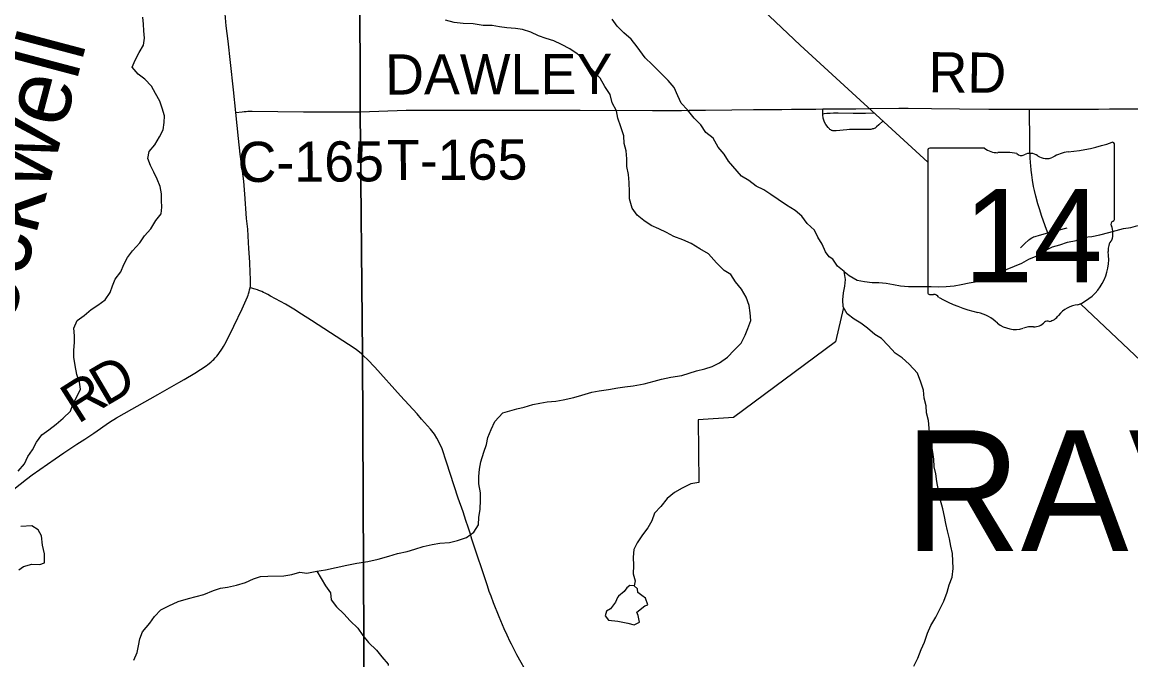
# Model space of a CAD drawing. Extents: x 0 to 34, y 0 to 22.
# Drawn here: x 4.548 to 6.114, y 15.953 to 16.855 of the extents above; entities that cross this region are included whole.
import ezdxf

# ---------------------------------------------------------------- set-up
doc = ezdxf.new("R2010")
doc.units = 0
for name, color, linetype in [('GM_X_Corporation', 7, 'Continuous'), ('GM_X_County_Road', 7, 'Continuous'), ('GM_X_County_Road_Text', 7, 'Continuous'), ('GM_X_Major_Lake', 7, 'Continuous'), ('GM_X_Major_Lake_Text', 7, 'Continuous'), ('GM_X_Minor_Lake', 7, 'Continuous'), ('GM_X_Minor_River', 7, 'Continuous'), ('GM_X_State_Shield', 7, 'Continuous'), ('GM_X_Township_Road', 7, 'Continuous'), ('GM_X_Township_Road_Text', 7, 'Continuous'), ('GM_X_Township_Text', 7, 'Continuous'), ('SH_Text', 7, 'Continuous')]:
    doc.layers.add(name, color=color, linetype=linetype)

msp = doc.modelspace()

# ---------------------------------------------------------------- linework, layer by layer
at = {"layer": 'GM_X_Corporation'}
for points in [[(2.1, 14.1), (5.0398, 14.1), (5.0411, 14.425), (5.0381, 14.4922), (5.0378, 14.5635), (5.0395, 14.6051), (5.0366, 14.7668), (5.0353, 14.97), (5.0288, 16.3849), (5.0258, 16.7286), (5.0235, 17.4989), (5.0235, 17.5004), (5.0224, 17.5004), (4.9697, 17.5009), (4.8689, 17.5017), (4.8462, 17.5018), (4.8313, 17.5017), (4.8033, 17.5014), (4.7857, 17.5004), (4.7764, 17.4996), (4.7708, 17.4988), (4.7665, 17.4977), (4.718, 17.4962), (3.7119, 17.4934)], [(5.0235, 17.4989), (5.0258, 16.7286), (5.0288, 16.3849), (5.0353, 14.97)]]:
    msp.add_lwpolyline(points, dxfattribs=at)
at = {"layer": 'GM_X_County_Road'}
for points in [[(4.8499, 16.7267), (4.8465, 16.7588), (4.8424, 16.7977), (4.8391, 16.8279), (4.8365, 16.8495), (4.835, 16.8662)], [(4.8499, 16.7267), (4.8591, 16.728), (4.8617, 16.7283), (4.8644, 16.7285), (4.8671, 16.7287), (4.873, 16.7287), (4.9456, 16.7279), (5.026, 16.728)], [(4.8701, 16.4792), (4.8705, 16.4816), (4.8707, 16.4839), (4.8708, 16.4864), (4.8708, 16.489), (4.8708, 16.4919), (4.8703, 16.5005), (4.8696, 16.5155), (4.8685, 16.5346), (4.8681, 16.5433), (4.8668, 16.5619), (4.8653, 16.5773), (4.8628, 16.612), (4.8624, 16.6172), (4.862, 16.6244), (4.8614, 16.6293), (4.8609, 16.6336), (4.8563, 16.668), (4.8537, 16.6902), (4.8499, 16.7267)], [(4.5363, 16.1946), (4.5544, 16.2088), (4.5624, 16.2148), (4.5948, 16.2376), (4.607, 16.246), (4.6256, 16.258), (4.6368, 16.2652), (4.6493, 16.2737), (4.6718, 16.2891), (4.6814, 16.2952), (4.6922, 16.3015), (4.7398, 16.3282), (4.7694, 16.3452), (4.777, 16.3496), (4.7919, 16.3585), (4.8081, 16.3689), (4.8106, 16.3708), (4.8125, 16.3722), (4.8151, 16.3744), (4.8172, 16.3762), (4.819, 16.378), (4.821, 16.3801), (4.8231, 16.3825), (4.825, 16.3848), (4.8271, 16.3877), (4.8293, 16.3908), (4.831, 16.3936), (4.8325, 16.396), (4.8344, 16.3996), (4.8366, 16.4036), (4.8471, 16.4248), (4.8588, 16.4495), (4.8664, 16.4662), (4.8673, 16.4689), (4.868, 16.4708), (4.8687, 16.4735), (4.8694, 16.4762), (4.8701, 16.4792)], [(5.029, 16.3843), (5.0273, 16.3858), (5.0222, 16.3899), (5.0184, 16.3927), (4.957, 16.4329), (4.9429, 16.4421), (4.9319, 16.4491), (4.9201, 16.456), (4.8991, 16.4675), (4.8954, 16.4695), (4.8915, 16.4715), (4.8892, 16.4725), (4.8866, 16.4737), (4.8827, 16.4754), (4.8804, 16.4762), (4.8774, 16.4772), (4.8752, 16.4779), (4.8728, 16.4786), (4.8701, 16.4792)], [(5.2632, 15.9313), (5.247, 15.9603), (5.2435, 15.9669), (5.2393, 15.9754), (5.2376, 15.9787), (5.2332, 15.9883), (5.2291, 15.9973), (5.222, 16.0139), (5.2139, 16.034), (5.2104, 16.0433), (5.208, 16.0498), (5.2053, 16.0577), (5.1835, 16.1237), (5.1808, 16.1322), (5.178, 16.1409), (5.1749, 16.1504), (5.1709, 16.1624), (5.1641, 16.1818), (5.1584, 16.1994), (5.1476, 16.2329), (5.1415, 16.2514), (5.1382, 16.2588), (5.1341, 16.2666), (5.1304, 16.2723), (5.1251, 16.2793), (5.1123, 16.2937), (5.1061, 16.3009), (5.0825, 16.3264), (5.0461, 16.367), (5.0361, 16.3777), (5.0309, 16.3827), (5.0299, 16.3835), (5.029, 16.3843)]]:
    msp.add_lwpolyline(points, dxfattribs=at)
at = {"layer": 'GM_X_Major_Lake'}
msp.add_lwpolyline([(4.5428, 16.22), (4.5515, 16.2303), (4.5563, 16.2406), (4.5627, 16.2501), (4.5683, 16.2611), (4.5761, 16.2714), (4.5859, 16.2783), (4.5961, 16.2864), (4.6062, 16.2948), (4.6164, 16.3047), (4.6197, 16.3142), (4.626, 16.326), (4.6305, 16.3359), (4.6293, 16.3458), (4.6254, 16.3567), (4.623, 16.3692), (4.6214, 16.381), (4.6214, 16.3908), (4.6224, 16.4018), (4.622, 16.4113), (4.6211, 16.4223), (4.6259, 16.433), (4.6357, 16.4399), (4.6455, 16.4487), (4.6553, 16.4548), (4.6655, 16.4621), (4.6726, 16.4724), (4.6759, 16.4819), (4.6796, 16.4914), (4.6875, 16.5017), (4.6919, 16.5123), (4.6968, 16.5219), (4.7039, 16.5314), (4.7144, 16.5429), (4.7211, 16.5528), (4.7298, 16.5627), (4.7372, 16.5741), (4.7444, 16.5837), (4.7454, 16.5931), (4.745, 16.6026), (4.7449, 16.6121), (4.7433, 16.6223), (4.7387, 16.6325), (4.7344, 16.6424), (4.7294, 16.6522), (4.7256, 16.662), (4.7274, 16.6719), (4.7356, 16.6814), (4.742, 16.6925), (4.7472, 16.7024), (4.7486, 16.7126), (4.7493, 16.7221), (4.7462, 16.7331), (4.7427, 16.7429), (4.7366, 16.7539), (4.7308, 16.764), (4.7217, 16.7742), (4.7122, 16.781), (4.7037, 16.7911), (4.7078, 16.801), (4.7134, 16.8117), (4.7194, 16.822), (4.7208, 16.8318), (4.72, 16.8425), (4.7195, 16.8519), (4.7187, 16.8618)], dxfattribs=at)
at = {"layer": 'GM_X_Minor_Lake'}
msp.add_line((5.389, 16.0415), (5.3864, 16.0347), dxfattribs=at)
for points in [[(4.5436, 16.0804), (4.55, 16.0854), (4.5617, 16.0885), (4.573, 16.0879), (4.5798, 16.0906), (4.5797, 16.1031), (4.577, 16.1156), (4.5754, 16.1288), (4.5707, 16.1371), (4.562, 16.1428), (4.5465, 16.1419)], [(5.3864, 16.0347), (5.3793, 16.0255), (5.3733, 16.022), (5.3714, 16.0156), (5.3764, 16.0092), (5.3897, 16.0081), (5.4037, 16.0052), (5.4124, 16.0026), (5.4203, 16.0065), (5.418, 16.0159), (5.4161, 16.0209), (5.4277, 16.0297), (5.4319, 16.0312), (5.4288, 16.0407), (5.4234, 16.0444), (5.4177, 16.0485), (5.4173, 16.0535), (5.4124, 16.058), (5.4063, 16.0583), (5.4022, 16.0549), (5.3984, 16.0499), (5.3905, 16.0434), (5.389, 16.0415)]]:
    msp.add_lwpolyline(points, dxfattribs=at)
at = {"layer": 'GM_X_Minor_River'}
for p, q in [((5.7081, 16.4513), (5.6969, 16.403)), ((5.6969, 16.403), (5.5528, 16.2957))]:
    msp.add_line(p, q, dxfattribs=at)
for points in [[(5.5558, 16.4876), (5.5493, 16.4981), (5.5398, 16.5037), (5.5287, 16.5146), (5.5177, 16.5271), (5.5055, 16.5342), (5.4929, 16.5417), (5.4812, 16.5469), (5.4686, 16.5517), (5.458, 16.5573), (5.4474, 16.5625), (5.4367, 16.5674), (5.4264, 16.5741), (5.4169, 16.5817), (5.4097, 16.5915), (5.4058, 16.6051), (5.4061, 16.6149), (5.4056, 16.6282), (5.4047, 16.6392), (5.402, 16.6505), (5.4023, 16.6615), (5.4011, 16.6725), (5.3983, 16.6831), (5.3979, 16.6937), (5.3936, 16.7066), (5.3897, 16.7191), (5.3878, 16.7293), (5.3816, 16.7406), (5.3789, 16.7524), (5.3712, 16.7637), (5.3647, 16.7754), (5.3494, 16.7916), (5.3414, 16.8021), (5.3319, 16.81), (5.3216, 16.8168), (5.3098, 16.8231), (5.2992, 16.8283), (5.2882, 16.8313), (5.2775, 16.8354), (5.2665, 16.8406), (5.2548, 16.8443), (5.2449, 16.8458), (5.2328, 16.8464), (5.2222, 16.8482), (5.2119, 16.85), (5.1991, 16.8499), (5.1854, 16.8521), (5.1711, 16.8528), (5.1585, 16.8542), (5.146, 16.8575)], [(5.6879, 16.5229), (5.683, 16.5302), (5.678, 16.5408), (5.6719, 16.5506), (5.6673, 16.5605), (5.657, 16.5702), (5.6493, 16.5804), (5.6398, 16.5883), (5.6276, 16.5958), (5.6158, 16.604), (5.6056, 16.6112), (5.5957, 16.6175), (5.585, 16.6228), (5.5747, 16.6306), (5.5641, 16.637), (5.5458, 16.6581), (5.5396, 16.6679), (5.5312, 16.6781), (5.5239, 16.6905), (5.5136, 16.6988), (5.5067, 16.7094), (5.4972, 16.7188), (5.4877, 16.7305), (5.4789, 16.7402), (5.4743, 16.7504), (5.4692, 16.7622), (5.4608, 16.772), (5.4494, 16.7836), (5.4379, 16.7949), (5.428, 16.8043), (5.4169, 16.8198), (5.4081, 16.8307), (5.3982, 16.8393), (5.3887, 16.8488), (5.3814, 16.8586)], [(5.709, 16.502), (5.7162, 16.4964), (5.7276, 16.49), (5.7379, 16.4882), (5.7485, 16.4868), (5.7583, 16.4868), (5.7685, 16.4858), (5.7788, 16.4836), (5.7886, 16.4821), (5.8, 16.4811), (5.8098, 16.4812), (5.8208, 16.4809), (5.8322, 16.481), (5.8428, 16.4807), (5.853, 16.4811), (5.8643, 16.482), (5.8745, 16.4839), (5.8859, 16.4863), (5.8968, 16.4879), (5.9078, 16.4922), (5.9183, 16.496), (5.9285, 16.4995), (5.9394, 16.5057), (5.9496, 16.5095), (5.9602, 16.5138), (5.97, 16.5196), (5.9802, 16.5238), (5.9919, 16.5315), (6.0032, 16.5369), (6.0137, 16.54), (6.0247, 16.5435), (6.0368, 16.5459), (6.0481, 16.5509), (6.0587, 16.5517), (6.0704, 16.5541), (6.0829, 16.5572), (6.0931, 16.5599), (6.1036, 16.563), (6.1138, 16.5646), (6.1237, 16.567)], [(5.7909, 16.3802), (5.7811, 16.3869), (5.7715, 16.3975), (5.762, 16.4076), (5.7525, 16.4132), (5.7422, 16.4223), (5.7327, 16.429), (5.7231, 16.435), (5.7132, 16.4425), (5.7075, 16.4523), (5.7074, 16.4622), (5.7081, 16.472), (5.7099, 16.4815), (5.711, 16.491), (5.709, 16.502), (5.6995, 16.5095), (5.6929, 16.5197), (5.6879, 16.5229)], [(4.7058, 15.9528), (4.7106, 15.9638), (4.7125, 15.9733), (4.7146, 15.9832), (4.7184, 15.9931), (4.7285, 16.0049), (4.7352, 16.0144), (4.7442, 16.024), (4.7552, 16.0294), (4.7687, 16.0359), (4.7831, 16.0398), (4.794, 16.0426), (4.805, 16.0457), (4.8186, 16.0511), (4.8284, 16.0546), (4.8382, 16.0562), (4.8511, 16.0589), (4.8635, 16.0624), (4.8748, 16.0678), (4.885, 16.071), (4.8952, 16.0714), (4.9176, 16.072), (4.9293, 16.074), (4.9402, 16.0771), (4.9501, 16.0756), (4.9645, 16.0784), (4.9765, 16.0804), (4.9917, 16.0839), (5.0068, 16.0871), (5.0211, 16.0898), (5.0363, 16.0922), (5.051, 16.0958), (5.0661, 16.0997), (5.0782, 16.1035), (5.0918, 16.1063), (5.1027, 16.1098), (5.1144, 16.1133), (5.1273, 16.1161), (5.1382, 16.118), (5.1519, 16.1193), (5.1632, 16.122), (5.1756, 16.1263), (5.1862, 16.1336), (5.1925, 16.1442), (5.1932, 16.1549), (5.195, 16.1659), (5.1957, 16.1795), (5.1956, 16.1894), (5.1932, 16.2023), (5.1931, 16.2125), (5.1942, 16.2228), (5.196, 16.233), (5.2004, 16.2467), (5.2038, 16.2577), (5.2059, 16.2676), (5.2104, 16.279), (5.2156, 16.2904), (5.2272, 16.3023), (5.2371, 16.3054), (5.2469, 16.3081), (5.2571, 16.3104), (5.2695, 16.314), (5.2794, 16.3163), (5.2899, 16.3179), (5.3017, 16.3188), (5.3123, 16.3207), (5.3274, 16.3243), (5.3387, 16.3274), (5.3527, 16.3317), (5.3633, 16.3333), (5.3761, 16.3353), (5.3893, 16.3376), (5.3995, 16.3392), (5.4113, 16.3408), (5.4268, 16.3432), (5.4407, 16.3471), (5.4513, 16.3499), (5.4645, 16.3526), (5.4797, 16.355), (5.4902, 16.3585), (5.5004, 16.3616), (5.5125, 16.3644), (5.5227, 16.3679), (5.5333, 16.3729), (5.5442, 16.3813), (5.5539, 16.3909), (5.5637, 16.4008), (5.5693, 16.4122), (5.573, 16.4217), (5.5771, 16.4331), (5.5762, 16.4437), (5.575, 16.4543), (5.5707, 16.4661), (5.5642, 16.477), (5.5558, 16.4876)], [(5.8076, 15.9443), (5.8132, 15.9557), (5.8177, 15.9678), (5.8225, 15.9781), (5.8266, 15.991), (5.8314, 16.0017), (5.8385, 16.0135), (5.8448, 16.0257), (5.8497, 16.0363), (5.8545, 16.0489), (5.8574, 16.0595), (5.8615, 16.0702), (5.8629, 16.0823), (5.862, 16.1035), (5.86, 16.1138), (5.8581, 16.1244), (5.8553, 16.1357), (5.8526, 16.1459), (5.8506, 16.1558), (5.8483, 16.1668), (5.8448, 16.1804), (5.8424, 16.1925), (5.84, 16.2054), (5.8388, 16.2164), (5.8361, 16.2262), (5.8356, 16.2368), (5.8344, 16.247), (5.8324, 16.2573), (5.8301, 16.2694), (5.8292, 16.2807), (5.828, 16.2917), (5.8256, 16.3023), (5.8248, 16.3122), (5.8221, 16.3232), (5.8212, 16.3345), (5.8173, 16.3459), (5.8127, 16.3583), (5.8009, 16.3711), (5.7909, 16.3802)], [(5.5528, 16.2957), (5.5029, 16.2923), (5.5039, 16.2039), (5.4926, 16.2023), (5.4802, 16.1958), (5.4696, 16.1896), (5.4591, 16.1812), (5.4501, 16.1701), (5.4411, 16.1606), (5.4374, 16.1499), (5.4318, 16.14), (5.4243, 16.1301), (5.4168, 16.1187), (5.4123, 16.1092), (5.4113, 16.0985), (5.4114, 16.0868), (5.4111, 16.075), (5.4142, 16.0652), (5.4124, 16.058)], [(4.9645, 16.0784), (4.9767, 16.058), (4.9836, 16.0478), (4.9845, 16.038), (4.9921, 16.0282), (5.0024, 16.0184), (5.0116, 16.0082), (5.0222, 15.9981), (5.0295, 15.9875), (5.0375, 15.9777), (5.0486, 15.9672), (5.0562, 15.9574), (5.065, 15.9472), (5.065, 15.9453)]]:
    msp.add_lwpolyline(points, dxfattribs=at)
at = {"layer": 'GM_X_State_Shield'}
for p, q in [((5.9072, 16.6765), (5.83, 16.6765)), ((6.0911, 16.5768), (6.0911, 16.6815)), ((5.8274, 16.6731), (5.8274, 16.4729)), ((6.091, 16.5768), (6.0911, 16.5768))]:
    msp.add_line(p, q, dxfattribs=at)
for centre, radius, start, end in [((5.8304, 16.6735), 0.00305, 98.1301, 188.1301), ((5.9256, 16.6997), 0.0296, 231.6195, 271.1119), ((5.9971, 16.9493), 0.2796, 275.8445, 288.9065), ((6.0881, 16.6819), 0.00294, 351.8621, 97.738), ((5.9354, 16.5642), 0.1064, 80.4867, 94.9883), ((5.9596, 16.6745), 0.00855, 219.7921, 297.1024), ((5.9721, 16.6514), 0.0178, 54.4667, 119.1411), ((5.995, 16.6831), 0.0214, 233.8562, 294.8282), ((6.0328, 16.6154), 0.0563, 97.3462, 120.7689), ((6.0904, 16.5691), 0.00454, 107.944, 210.337), ((6.0615, 16.5559), 0.0273, 340.033, 23.6496), ((6.0879, 16.5764), 0.00314, 289.6038, 7.7341), ((6.1016, 16.533), 0.0198, 136.8065, 186.9296), ((6.0128, 16.5197), 0.0699, 292.3089, 8.9858), ((5.8304, 16.4725), 0.00308, 171.9584, 258.3066), ((5.8309, 16.493), 0.0235, 267.339, 280.6039), ((5.8357, 16.4614), 0.00848, 29.7484, 93.2717), ((5.9428, 16.6412), 0.2019, 240.4129, 257.1985), ((5.8826, 16.383), 0.0632, 47.1842, 75.836), ((5.9938, 16.4535), 0.0226, 282.8732, 323.2771), ((6.0423, 16.4168), 0.0383, 94.4031, 142.5768), ((5.9509, 16.4604), 0.0401, 230.7004, 286.2918), ((5.977, 16.4454), 0.0214, 268.777, 315.5493), ((5.9963, 16.426), 0.00601, 65.7517, 132.6484), ((5.9741, 16.3912), 0.0329, 85.6951, 111.2099)]:
    msp.add_arc(centre, radius, start, end, dxfattribs=at)
at = {"layer": 'GM_X_Township_Road'}
msp.add_line((5.9966, 16.5566), (6.0242, 16.564), dxfattribs=at)
for points in [[(5.026, 16.728), (5.0908, 16.73), (5.114, 16.7303), (5.1556, 16.7304), (5.1824, 16.7301), (5.198, 16.7301), (5.2131, 16.7302), (5.2519, 16.7303), (5.3362, 16.7302), (5.4386, 16.7296), (5.4525, 16.7297), (5.4703, 16.7297), (5.4793, 16.7298), (5.4901, 16.73), (5.4921, 16.73)], [(5.4921, 16.73), (5.5132, 16.7302), (5.5507, 16.7306), (5.5812, 16.731), (5.5955, 16.7311), (5.6083, 16.7312), (5.6212, 16.7313), (5.6347, 16.7314), (5.6581, 16.7316), (5.6689, 16.7318), (5.6789, 16.7319)], [(5.6789, 16.7319), (5.7258, 16.7322), (5.7448, 16.7324)], [(5.764, 16.7149), (5.758, 16.7094), (5.7549, 16.7066), (5.7538, 16.7057), (5.7528, 16.705), (5.7517, 16.7045), (5.7506, 16.704), (5.7493, 16.7036), (5.7481, 16.7033), (5.7466, 16.7031), (5.7432, 16.7029), (5.7395, 16.7028), (5.7296, 16.7028), (5.7209, 16.7028), (5.7168, 16.7027), (5.7128, 16.7024), (5.6978, 16.701), (5.6963, 16.7009), (5.695, 16.701), (5.6941, 16.701), (5.6931, 16.7011), (5.6923, 16.7013), (5.6914, 16.7016), (5.6901, 16.7023), (5.6889, 16.7031), (5.6882, 16.7037), (5.6866, 16.7055), (5.6834, 16.7099), (5.6815, 16.7132), (5.6803, 16.716), (5.6798, 16.7175), (5.6796, 16.7189), (5.6793, 16.7205), (5.6792, 16.722), (5.6791, 16.725), (5.6789, 16.7319)], [(5.6791, 16.725), (5.6808, 16.7253), (5.6846, 16.7258), (5.6894, 16.7261), (5.6943, 16.7263), (5.7007, 16.7264), (5.7218, 16.7262), (5.7394, 16.7262), (5.7513, 16.7265)], [(5.7448, 16.7324), (5.7865, 16.7329), (5.7994, 16.7329), (5.8327, 16.7326), (5.8722, 16.7321), (5.9135, 16.7317), (5.971, 16.7317)], [(5.971, 16.7317), (6.0017, 16.7317), (6.0681, 16.7318), (6.0837, 16.7319), (6.1029, 16.732), (6.1264, 16.7323), (6.161, 16.7326)], [(5.9966, 16.5566), (5.9948, 16.5615), (5.9885, 16.5797), (5.9849, 16.5909), (5.9828, 16.5977), (5.9797, 16.6086), (5.9778, 16.6165), (5.9766, 16.6225), (5.9751, 16.6315), (5.9741, 16.6386), (5.9732, 16.6454), (5.9726, 16.6519), (5.9723, 16.6556), (5.9718, 16.6633), (5.9716, 16.6678), (5.9715, 16.67), (5.9714, 16.6737), (5.9712, 16.6884), (5.971, 16.7281), (5.971, 16.7317)], [(5.9582, 16.5357), (5.9637, 16.5413), (5.9697, 16.5468), (5.9712, 16.548), (5.9733, 16.5494), (5.9749, 16.5503), (5.9766, 16.5511), (5.9789, 16.5518), (5.9849, 16.5535), (5.9966, 16.5566)]]:
    msp.add_lwpolyline(points, dxfattribs=at)
at = {"layer": 'SH_Text'}
for points in [[(5.2632, 17.1919), (5.3023, 17.152), (5.3786, 17.078), (5.4473, 17.0114), (5.6471, 16.8219), (5.8274, 16.6565)], [(6.0436, 16.4561), (6.1622, 16.3439), (6.2259, 16.279), (6.2997, 16.2029), (6.3775, 16.1225), (6.4588, 16.0391), (6.4804, 16.0186), (6.5205, 15.9884), (6.5845, 15.9575), (6.6499, 15.9422), (6.7146, 15.9393), (6.7966, 15.9403), (7.822, 15.947)]]:
    msp.add_lwpolyline(points, dxfattribs=at)

# ---------------------------------------------------------------- texts
at = {"layer": 'GM_X_County_Road_Text'}
for s, height, rotation, p in [('C-165', 0.05682, 0.2768, (4.8525, 16.6286)), ('D', 0.0568, 30.434, (4.6659, 16.3108)), ('R', 0.0568, 32.5014, (4.627, 16.286))]:
    msp.add_text(s, height=height, rotation=rotation, dxfattribs=at).set_placement(p)
at = {"layer": 'GM_X_Major_Lake_Text'}
msp.add_text('Rockwell', height=0.09473, rotation=75.1742, dxfattribs=at).set_placement((4.5097, 16.3347))
at = {"layer": 'GM_X_State_Shield'}
msp.add_text('14', height=0.13184, dxfattribs=at).set_placement((5.878, 16.4871))
at = {"layer": 'GM_X_Township_Road_Text'}
for s, rotation, p in [('DAWLEY', 0.1553, (5.0609, 16.7522)), ('RD', 359.5089, (5.8281, 16.7555)), ('T-165', 0.2739, (5.0635, 16.6312))]:
    msp.add_text(s, height=0.05682, rotation=rotation, dxfattribs=at).set_placement(p)
at = {"layer": 'GM_X_Township_Text'}
msp.add_text('RAVENNA', height=0.17045, rotation=0, dxfattribs=at).set_placement((5.7941, 16.1073))

doc.saveas('drawing.dxf')
